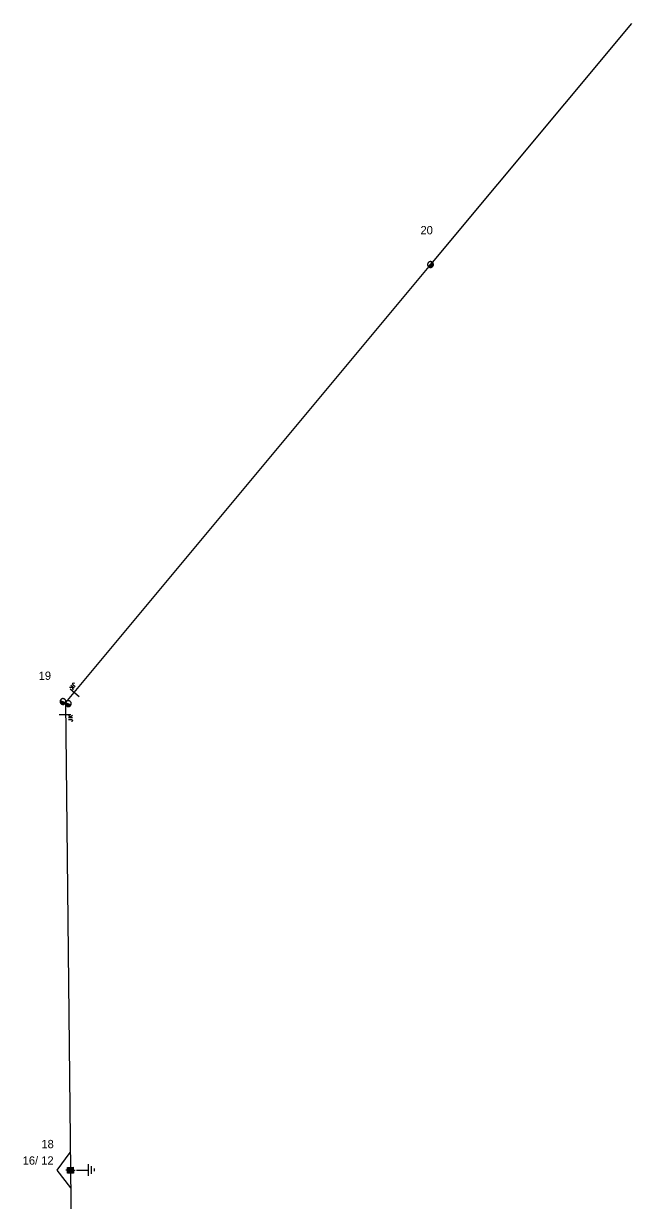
# Model space of a CAD drawing. Extents: x -788491 to -785797, y -1154753 to -1152002.
# Drawn here: x -786710.7 to -786582.7, y -1152250.1 to -1152002.4 of the extents above; entities that cross this region are included whole.
import ezdxf

# ---------------------------------------------------------------- set-up
doc = ezdxf.new("R2010")
doc.units = 0
for name, color, linetype in [('Vrstva 1', 7, 'Continuous'), ('Vrstva 13', 7, 'Continuous'), ('Vrstva 14', 7, 'Continuous'), ('Vrstva 15', 7, 'Continuous'), ('Vrstva 18', 7, 'Continuous'), ('Vrstva 2', 7, 'Continuous'), ('Vrstva 49', 7, 'Continuous')]:
    doc.layers.add(name, color=color, linetype=linetype)

# ---------------------------------------------------------------- blocks, each defined once
blk = doc.blocks.new('VN840')
at = {"layer": 'Vrstva 15'}
for points in [[(-0.01, 1.41), (-0.01, -1.09)], [(-1.51, -1.24), (-1.51, -1.15)], [(-1.48, -1.35), (-1.51, -1.24)], [(-1.33, -1.42), (-1.48, -1.35)], [(-1.27, -1.42), (-1.33, -1.42)], [(-1.13, -1.35), (-1.27, -1.42)], [(-1.09, -1.24), (-1.13, -1.35)], [(-1.09, -0.59), (-1.09, -1.24)], [(-0.68, -0.59), (-0.68, -1.42)], [(-0.68, -1.11), (-0.27, -0.59)], [(-0.54, -0.94), (-0.2, -1.42)]]:
    blk.add_lwpolyline(points, dxfattribs=at)
blk = doc.blocks.new('VN860')
at = {"layer": 'Vrstva 15'}
for points in [[(-3.74, 0), (0.01, 2.82)], [(0.01, 2.82), (3.76, 0)]]:
    blk.add_lwpolyline(points, dxfattribs=at)
blk = doc.blocks.new('VN440')
at = {"layer": 'Vrstva 2'}
for points in [[(1.22, 0), (1.21, 0.13), (1.19, 0.25), (1.16, 0.38), (1.11, 0.5), (1.05, 0.61), (0.98, 0.72), (0.9, 0.82), (0.81, 0.91), (0.71, 0.99), (0.6, 1.06), (0.49, 1.12), (0.37, 1.16), (0.25, 1.2), (0.12, 1.22), (-0.01, 1.22), (-0.14, 1.22), (-0.26, 1.2), (-0.39, 1.16), (-0.51, 1.12), (-0.62, 1.06), (-0.73, 0.99), (-0.83, 0.91), (-0.92, 0.82), (-1, 0.72), (-1.07, 0.61), (-1.13, 0.5), (-1.18, 0.38), (-1.21, 0.25), (-1.23, 0.13), (-1.24, 0), (-1.23, -0.13), (-1.21, -0.26), (-1.18, -0.38), (-1.13, -0.5), (-1.07, -0.62), (-1, -0.73), (-0.92, -0.83), (-0.83, -0.92), (-0.73, -1), (-0.62, -1.07), (-0.51, -1.13), (-0.39, -1.17), (-0.26, -1.2), (-0.14, -1.23), (-0.01, -1.23), (0.12, -1.23), (0.25, -1.2), (0.37, -1.17), (0.49, -1.13), (0.6, -1.07), (0.71, -1), (0.81, -0.92), (0.9, -0.83), (0.98, -0.73), (1.05, -0.62), (1.11, -0.5), (1.16, -0.38), (1.19, -0.26), (1.21, -0.13), (1.22, 0)], [(-1.24, 0), (1.22, 0)], [(-1.18, -0.34), (1.1, -0.34)], [(-1.01, -0.63), (0.97, -0.63)], [(-0.74, -0.92), (0.68, -0.92)]]:
    blk.add_lwpolyline(points, dxfattribs=at)
blk = doc.blocks.new('VN810')
at = {"layer": 'Vrstva 14'}
for points in [[(0, -1.25), (0, -3.75)], [(1.25, -3.75), (-1.25, -3.75)], [(0.77, -4.37), (-0.8, -4.37)], [(0, -5), (-0.25, -5)], [(0.27, -5), (0, -5)]]:
    blk.add_lwpolyline(points, dxfattribs=at)
blk = doc.blocks.new('VN450')
at = {"layer": 'Vrstva 2'}
for points in [[(0, 0), (-0.01, 0.13), (-0.03, 0.25), (-0.06, 0.38), (-0.11, 0.5), (-0.16, 0.61), (-0.23, 0.72), (-0.31, 0.82), (-0.4, 0.91), (-0.5, 0.99), (-0.61, 1.06), (-0.72, 1.11), (-0.84, 1.16), (-0.97, 1.19), (-1.09, 1.21), (-1.22, 1.22), (-1.35, 1.21), (-1.47, 1.19), (-1.59, 1.16), (-1.71, 1.11), (-1.83, 1.06), (-1.93, 0.99), (-2.03, 0.91), (-2.12, 0.82), (-2.2, 0.72), (-2.27, 0.61), (-2.33, 0.5), (-2.38, 0.38), (-2.41, 0.25), (-2.43, 0.13), (-2.44, 0), (-2.43, -0.13), (-2.41, -0.25), (-2.38, -0.38), (-2.33, -0.5), (-2.27, -0.61), (-2.2, -0.72), (-2.12, -0.82), (-2.03, -0.91), (-1.93, -0.99), (-1.83, -1.06), (-1.71, -1.11), (-1.59, -1.16), (-1.47, -1.19), (-1.35, -1.21), (-1.22, -1.22), (-1.09, -1.21), (-0.97, -1.19), (-0.84, -1.16), (-0.72, -1.11), (-0.61, -1.06), (-0.5, -0.99), (-0.4, -0.91), (-0.31, -0.82), (-0.23, -0.72), (-0.16, -0.61), (-0.11, -0.5), (-0.06, -0.38), (-0.03, -0.25), (-0.01, -0.13), (0, 0)], [(-2.44, 0), (2.44, 0)], [(2.44, 0), (2.43, 0.13), (2.41, 0.25), (2.38, 0.38), (2.33, 0.5), (2.27, 0.61), (2.2, 0.72), (2.12, 0.82), (2.03, 0.91), (1.94, 0.99), (1.83, 1.06), (1.71, 1.11), (1.6, 1.16), (1.47, 1.19), (1.35, 1.21), (1.22, 1.22), (1.09, 1.21), (0.97, 1.19), (0.84, 1.16), (0.72, 1.11), (0.61, 1.06), (0.5, 0.99), (0.4, 0.91), (0.31, 0.82), (0.23, 0.72), (0.16, 0.61), (0.11, 0.5), (0.06, 0.38), (0.03, 0.25), (0.01, 0.13), (0, 0), (0.01, -0.13), (0.03, -0.25), (0.06, -0.38), (0.11, -0.5), (0.16, -0.61), (0.23, -0.72), (0.31, -0.82), (0.4, -0.91), (0.5, -0.99), (0.61, -1.06), (0.72, -1.11), (0.84, -1.16), (0.97, -1.19), (1.09, -1.21), (1.22, -1.22), (1.35, -1.21), (1.47, -1.19), (1.6, -1.16), (1.71, -1.11), (1.83, -1.06), (1.94, -0.99), (2.03, -0.91), (2.12, -0.82), (2.2, -0.72), (2.27, -0.61), (2.33, -0.5), (2.38, -0.38), (2.41, -0.25), (2.43, -0.13), (2.44, 0)], [(-2.4, -0.31), (-0.04, -0.31)], [(-2.26, -0.61), (-0.17, -0.61)], [(-2.01, -0.92), (-0.42, -0.92)], [(0.04, -0.31), (2.4, -0.31)], [(0.17, -0.61), (2.27, -0.61)], [(0.42, -0.92), (2.02, -0.92)]]:
    blk.add_lwpolyline(points, dxfattribs=at)
blk = doc.blocks.new('VN470')
at = {"layer": 'Vrstva 2'}
for points in [[(-1.23, 1.22), (1.23, 1.22)], [(-1.23, -1.23), (-1.23, 1.22)], [(-0.92, 0.9), (0.92, 0.9)], [(-0.92, -0.95), (-0.92, 0.9)], [(-0.61, 0.61), (0.61, 0.61)], [(-0.61, -0.62), (-0.61, 0.61)], [(-0.31, -0.27), (-0.31, 0.34)], [(-0.31, 0.34), (0.31, 0.34)], [(0, 1.22), (0, 1.97)], [(0.31, 0.34), (0.31, -0.27)], [(0.61, 0.61), (0.61, -0.62)], [(0.92, 0.9), (0.92, -0.95)], [(1.23, 1.22), (1.23, -1.23)], [(1.23, -1.23), (-1.23, -1.23)], [(0.92, -0.95), (-0.92, -0.95)], [(0.61, -0.62), (-0.61, -0.62)], [(0.31, -0.27), (-0.31, -0.27)], [(0, -1.23), (0, -1.98)]]:
    blk.add_lwpolyline(points, dxfattribs=at)

msp = doc.modelspace()

# ---------------------------------------------------------------- linework, layer by layer
at = {"layer": 'Vrstva 1'}
msp.add_lwpolyline([(-786582.66, -1152002.36), (-786624.98, -1152053.08), (-786701.81, -1152145.29), (-786700.8, -1152243.72), (-786698.72, -1152417.16), (-786697.17, -1152540.35)], dxfattribs=at)

# ---------------------------------------------------------------- block references
at = {"layer": 'Vrstva 13'}
for name, p, xscale, yscale, rotation in [('VN440', (-786624.98, -1152053.08), 0.5, 0.49999999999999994, 49.92146666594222), ('VN450', (-786701.81, -1152145.29), 0.5000000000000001, 0.5000000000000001, -21.27708609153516), ('VN470', (-786700.8, -1152243.72), 0.49999999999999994, 0.4999999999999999, 90.96268054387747)]:
    msp.add_blockref(name, p, dxfattribs=dict(at, xscale=xscale, yscale=yscale, rotation=rotation))
at = {"layer": 'Vrstva 15', "rotation": 90.68462220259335}
msp.add_blockref('VN810', (-786700.8, -1152243.72), dxfattribs=at)
at = {"layer": 'Vrstva 18'}
for name, p, rotation in [('VN840', (-786700.03, -1152143.16), -129.79713606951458), ('VN840', (-786701.78, -1152147.78), 90.58615001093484), ('VN860', (-786700.8, -1152243.72), 90.68648335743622)]:
    msp.add_blockref(name, p, dxfattribs=dict(at, rotation=rotation))

# ---------------------------------------------------------------- texts
at = {"layer": 'Vrstva 14'}
for s, p in [('20', (-786627.09, -1152046.73)), ('19', (-786707.49, -1152140.51)), ('18', (-786706.92, -1152239.09))]:
    msp.add_text(s, height=1.75, dxfattribs=at).set_placement(p)
at = {"layer": 'Vrstva 49'}
msp.add_text('16/ 12', height=1.75, dxfattribs=at).set_placement((-786710.86, -1152242.55))

doc.saveas('drawing.dxf')
